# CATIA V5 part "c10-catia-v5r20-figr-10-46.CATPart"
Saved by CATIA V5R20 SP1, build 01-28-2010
Part number: Part1
Bounding box of the stored display mesh (mm): x -80.563 to 63.541, y -72 to 69, z -55 to 6.847
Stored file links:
  D:\v5_r20\psrt_files_downloaded\c10\c10-catia-v5r20-figr-10-46.CATPart
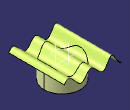
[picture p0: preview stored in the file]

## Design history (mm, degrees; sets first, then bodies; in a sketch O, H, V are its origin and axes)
Set1
  Sketch1 on xy-plane, origin (0, 0, 0), H (-1, 0, 0), V (0, -1, 0)
    circle A1 centre (0, 0) radius 45.985
  Extrude1: Element1 Sketch1, Lim1 56, Lim2 55, Direction xy-plane
  Sketch2 on zx-plane, origin (0, 0, 0), H (1, 0, 0), V (0, 0, -1)
    spline S1 through (-80.5635, 24.8913) (-73.6025, 19.8803) (-54.8525, -3.3629) (-35.1982, 19.8803) (-2.6271, -1.6506) (16.6996, 17.2854) (52.4104, -6.7877) (63.5409, 1.5862)
  Extrude2: Element1 Sketch2, Lim1 72, Lim2 69, Direction Sketch1.V
  Split1: ToCut Extrude1, Cutting Extrude2
Body1 (main body)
